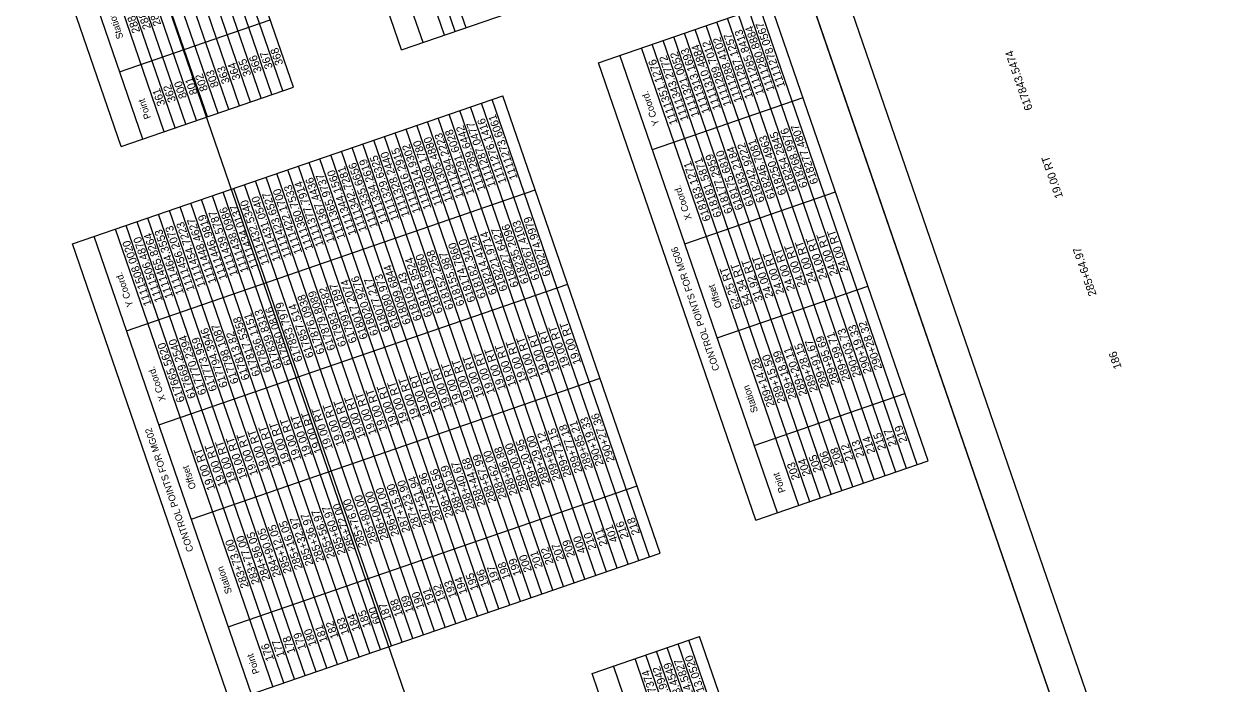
# Model space of a CAD drawing. Extents: x 1111039 to 1111836, y 617707 to 618808.
# Drawn here: x 1111305 to 1111836, y 618074 to 618364 of the extents above; entities that cross this region are included whole.
import ezdxf

# ---------------------------------------------------------------- set-up
doc = ezdxf.new("R2010")
doc.units = 0
for name, color, linetype in [('ANNOTATION', 7, 'Continuous'), ('BORDER', 7, 'Continuous'), ('CLIPS', 7, 'Continuous'), ('H_V CONTROLS', 7, 'Continuous'), ('PLOT BOUNDARY', 7, 'Continuous')]:
    doc.layers.add(name, color=color, linetype=linetype)

msp = doc.modelspace()

# ---------------------------------------------------------------- linework, layer by layer
at = {"layer": 'BORDER'}
msp.add_line((1111807.98, 617919.56), (1111547.52, 618675.97), dxfattribs=at)
at = {"layer": 'CLIPS'}
msp.add_lwpolyline([(1111807.98, 617919.56), (1111563.8, 618628.7), (1111310.4, 618541.44), (1111554.58, 617832.3)], close=True, dxfattribs=at)
at = {"layer": 'H_V CONTROLS'}
for p, q in [((1111494.82, 618360.94), (1111425.64, 618561.86)), ((1111499.55, 618362.57), (1111430.37, 618563.49)), ((1111480.64, 618356.06), (1111411.46, 618556.98)), ((1111490.09, 618359.31), (1111420.91, 618560.24)), ((1111471.18, 618352.8), (1111402, 618553.73)), ((1111418.96, 618334.82), (1111349.78, 618535.74)), ((1111423.69, 618336.45), (1111354.5, 618537.37)), ((1111423.69, 618336.45), (1111354.5, 618537.37)), ((1111404.78, 618329.94), (1111335.59, 618530.86)), ((1111409.51, 618331.56), (1111340.32, 618532.49)), ((1111414.23, 618333.19), (1111345.05, 618534.12)), ((1111390.59, 618325.05), (1111321.41, 618525.98)), ((1111395.32, 618326.68), (1111326.14, 618527.6)), ((1111400.05, 618328.31), (1111330.87, 618529.23)), ((1111371.68, 618318.54), (1111302.5, 618519.46)), ((1111376.41, 618320.17), (1111307.23, 618521.09)), ((1111381.14, 618321.8), (1111311.96, 618522.72)), ((1111385.87, 618323.43), (1111316.68, 618524.35)), ((1111357.5, 618313.66), (1111288.32, 618514.58)), ((1111366.96, 618316.91), (1111297.77, 618517.84)), ((1111348.05, 618310.4), (1111278.86, 618511.33)), ((1111471.18, 618352.8), (1111622.47, 618404.89)), ((1111557.73, 618347.19), (1111633.37, 618373.23)), ((1111697.82, 618170.68), (1111628.64, 618371.61)), ((1111702.55, 618172.31), (1111633.37, 618373.23)), ((1111702.55, 618172.31), (1111633.37, 618373.23)), ((1111347.33, 618343.21), (1111413.51, 618366)), ((1111683.64, 618165.8), (1111614.46, 618366.72)), ((1111688.37, 618167.43), (1111619.19, 618368.35)), ((1111693.1, 618169.06), (1111623.91, 618369.98)), ((1111669.46, 618160.92), (1111600.28, 618361.84)), ((1111674.19, 618162.54), (1111605, 618363.47)), ((1111678.91, 618164.17), (1111609.73, 618365.09)), ((1111650.55, 618154.4), (1111581.37, 618355.33)), ((1111655.28, 618156.03), (1111586.09, 618356.96)), ((1111660, 618157.66), (1111590.82, 618358.58)), ((1111664.73, 618159.29), (1111595.55, 618360.21)), ((1111636.37, 618149.52), (1111567.18, 618350.44)), ((1111645.82, 618152.78), (1111576.64, 618353.7)), ((1111626.91, 618146.27), (1111557.73, 618347.19)), ((1111348.05, 618310.4), (1111423.69, 618336.45)), ((1111326.61, 618267.61), (1111515.71, 618332.72)), ((1111575.44, 618128.54), (1111506.26, 618329.47)), ((1111580.17, 618130.17), (1111510.98, 618331.09)), ((1111584.9, 618131.8), (1111515.71, 618332.72)), ((1111584.9, 618131.8), (1111515.71, 618332.72)), ((1111581.43, 618309.08), (1111647.61, 618331.87)), ((1111561.26, 618123.66), (1111492.07, 618324.58)), ((1111565.98, 618125.29), (1111496.8, 618326.21)), ((1111570.71, 618126.91), (1111501.53, 618327.84)), ((1111542.35, 618117.15), (1111473.16, 618318.07)), ((1111547.07, 618118.78), (1111477.89, 618319.7)), ((1111551.8, 618120.4), (1111482.62, 618321.33)), ((1111556.53, 618122.03), (1111487.35, 618322.95)), ((1111528.16, 618112.26), (1111458.98, 618313.19)), ((1111532.89, 618113.89), (1111463.71, 618314.81)), ((1111537.62, 618115.52), (1111468.44, 618316.44)), ((1111513.98, 618107.38), (1111444.8, 618308.3)), ((1111518.71, 618109.01), (1111449.53, 618309.93)), ((1111523.44, 618110.64), (1111454.25, 618311.56)), ((1111499.8, 618102.5), (1111430.62, 618303.42)), ((1111504.53, 618104.12), (1111435.34, 618305.05)), ((1111509.25, 618105.75), (1111440.07, 618306.68)), ((1111480.89, 618095.99), (1111411.7, 618296.91)), ((1111485.62, 618097.61), (1111416.43, 618298.54)), ((1111490.34, 618099.24), (1111421.16, 618300.16)), ((1111495.07, 618100.87), (1111425.89, 618301.79)), ((1111350.31, 618229.5), (1111529.96, 618291.35)), ((1111466.71, 618091.1), (1111397.52, 618292.02)), ((1111471.43, 618092.73), (1111402.25, 618293.65)), ((1111476.16, 618094.36), (1111406.98, 618295.28)), ((1111452.52, 618086.22), (1111383.34, 618287.14)), ((1111457.25, 618087.85), (1111388.07, 618288.77)), ((1111461.98, 618089.47), (1111392.79, 618290.4)), ((1111595.67, 618267.71), (1111661.86, 618290.5)), ((1111438.34, 618081.34), (1111369.16, 618282.26)), ((1111443.07, 618082.96), (1111373.88, 618283.89)), ((1111447.79, 618084.59), (1111378.61, 618285.51)), ((1111419.43, 618074.82), (1111350.25, 618275.75)), ((1111424.16, 618076.45), (1111354.97, 618277.37)), ((1111428.88, 618078.08), (1111359.7, 618279)), ((1111433.61, 618079.71), (1111364.43, 618280.63)), ((1111405.25, 618069.94), (1111336.06, 618270.86)), ((1111414.7, 618073.2), (1111345.52, 618274.12)), ((1111395.79, 618066.68), (1111326.61, 618267.61)), ((1111364.55, 618188.13), (1111544.2, 618249.99)), ((1111609.91, 618226.34), (1111676.1, 618249.13)), ((1111378.79, 618146.76), (1111558.44, 618208.62)), ((1111626.19, 618179.07), (1111692.38, 618201.86)), ((1111626.91, 618146.27), (1111702.55, 618172.31)), ((1111395.07, 618099.49), (1111574.72, 618161.35)), ((1111395.79, 618066.68), (1111584.9, 618131.8)), ((1111554.89, 618079), (1111602.17, 618095.28)), ((1111671.35, 617894.36), (1111602.17, 618095.28)), ((1111671.35, 617894.36), (1111602.17, 618095.28)), ((1111657.17, 617889.47), (1111587.98, 618090.4)), ((1111661.89, 617891.1), (1111592.71, 618092.02)), ((1111666.62, 617892.73), (1111597.44, 618093.65)), ((1111642.98, 617884.59), (1111573.8, 618085.51)), ((1111647.71, 617886.22), (1111578.53, 618087.14)), ((1111652.44, 617887.85), (1111583.26, 618088.77)), ((1111633.53, 617881.33), (1111564.35, 618082.26)), ((1111624.07, 617878.08), (1111554.89, 618079))]:
    msp.add_line(p, q, dxfattribs=at)
at = {"layer": 'PLOT BOUNDARY'}
msp.add_lwpolyline([(1111835.61, 617886.27), (1111558.88, 618689.96), (1111038.85, 618510.9), (1111315.58, 617707.21)], close=True, dxfattribs=at)

# ---------------------------------------------------------------- texts
at = {"layer": 'ANNOTATION'}
for s, height, p in [('288+71.40', 3.516, (1111356.41, 618360.83)), ('288+79.37', 3.516, (1111361.15, 618362.47)), ('289+13.25', 3.45, (1111365.62, 618364)), ('1111285.8413', 3.5156, (1111630.49, 618333.68)), ('1111280.8884', 3.5156, (1111635.17, 618335.29)), ('1111278.0567', 3.5156, (1111639.81, 618336.89)), ('1111310.4884', 3.5156, (1111611.54, 618327.15)), ('1111289.7012', 3.5156, (1111616.26, 618328.78)), ('1111288.4102', 3.5156, (1111620.97, 618330.4)), ('1111287.1257', 3.5156, (1111625.73, 618332.04)), ('366', 3.516, (1111409.89, 618343.44)), ('367', 3.516, (1111414.72, 618345.11)), ('368', 3.516, (1111419.29, 618346.68)), ('1111343.2772', 3.5156, (1111597.38, 618322.28)), ('1111321.0052', 3.5156, (1111602.17, 618323.93)), ('1111313.1693', 3.5156, (1111606.82, 618325.53)), ('617843.5474', 3.5156, (1111748.59, 618326.93)), ('363', 3.516, (1111395.84, 618338.61)), ('364', 3.516, (1111400.53, 618340.22)), ('365', 3.516, (1111405.24, 618341.84)), ('1111351.1276', 3.5156, (1111592.58, 618320.63)), ('800', 3.516, (1111376.97, 618332.11)), ('801', 3.516, (1111381.74, 618333.75)), ('802', 3.516, (1111386.21, 618335.29)), ('803', 3.516, (1111390.98, 618336.93)), ('361', 3.516, (1111367.44, 618328.83)), ('362', 3.516, (1111372.17, 618330.46)), ('1111273.6061', 3.5156, (1111522.27, 618296.42)), ('1111291.6028', 3.5156, (1111503.24, 618289.86)), ('1111289.6442', 3.5156, (1111508.11, 618291.54)), ('1111287.0477', 3.5156, (1111512.68, 618293.11)), ('1111276.1416', 3.5156, (1111517.4, 618294.74)), ('618268.9976', 3.5156, (1111649.76, 618292.9)), ('618277.4807', 3.5156, (1111654.41, 618294.5)), ('1111308.1780', 3.5156, (1111489.16, 618285.02)), ('1111305.4880', 3.5156, (1111493.81, 618286.61)), ('1111294.2223', 3.5156, (1111498.6, 618288.27)), ('618246.7081', 3.5156, (1111635.57, 618288.01)), ('618250.4963', 3.5156, (1111640.33, 618289.65)), ('618254.2845', 3.5156, (1111645.08, 618291.29)), ('1111328.2440', 3.5156, (1111474.84, 618280.08)), ('1111316.2915', 3.5156, (1111479.64, 618281.74)), ('1111314.9302', 3.5156, (1111484.39, 618283.37)), ('618175.6810', 3.5156, (1111621.41, 618283.14)), ('618183.2184', 3.5156, (1111626.13, 618284.76)), ('618242.9222', 3.5156, (1111630.85, 618286.39)), ('1111335.6656', 3.5156, (1111460.8, 618275.25)), ('1111334.2619', 3.5156, (1111465.48, 618276.86)), ('1111329.6325', 3.5156, (1111470.19, 618278.48)), ('618183.1271', 3.5156, (1111607.18, 618278.24)), ('618181.5871', 3.5156, (1111611.97, 618279.89)), ('618177.2959', 3.5156, (1111616.77, 618281.54)), ('19.00 RT', 3.516, (1111761.9, 618288.3)), ('1111367.4436', 3.5156, (1111441.9, 618268.74)), ('1111365.9737', 3.5156, (1111446.51, 618270.33)), ('1111344.1560', 3.5156, (1111451.43, 618272.02)), ('1111342.7281', 3.5156, (1111456.02, 618273.6)), ('1111422.1700', 3.5156, (1111427.61, 618263.82)), ('1111380.7533', 3.5156, (1111432.43, 618265.48)), ('1111377.7914', 3.5156, (1111437.07, 618267.08)), ('1111432.5340', 3.5156, (1111413.23, 618258.87)), ('1111431.0540', 3.5156, (1111418.18, 618260.57)), ('1111423.6527', 3.5156, (1111422.93, 618262.21)), ('1111439.5787', 3.5156, (1111399.37, 618254.1)), ('1111438.0986', 3.5156, (1111404.06, 618255.71)), ('1111434.0137', 3.45, (1111408.56, 618257.24)), ('1111456.2073', 3.5156, (1111380.31, 618247.54)), ('1111454.7223', 3.5156, (1111385.14, 618249.2)), ('1111448.4627', 3.5156, (1111389.92, 618250.84)), ('1111446.9819', 3.5156, (1111394.66, 618252.47)), ('618235.2096', 3.5156, (1111527.28, 618250.73)), ('618267.4103', 3.5156, (1111532, 618252.35)), ('618274.9979', 3.5156, (1111536.87, 618254.03)), ('1111506.4870', 3.5156, (1111366.3, 618242.71)), ('1111465.8264', 3.5156, (1111370.91, 618244.3)), ('1111464.3553', 3.5156, (1111375.63, 618245.92)), ('618214.4124', 3.5156, (1111513.2, 618245.88)), ('618221.9714', 3.5156, (1111517.84, 618247.48)), ('618227.6427', 3.5156, (1111522.71, 618249.15)), ('24.00 RT', 3.516, (1111663.07, 618254.27)), ('24.00 RT', 3.516, (1111667.71, 618255.87)), ('1111508.0020', 3.5156, (1111361.46, 618241.05)), ('618152.2258', 3.5156, (1111494.23, 618239.35)), ('618174.7860', 3.5156, (1111503.76, 618242.63)), ('618182.3410', 3.5156, (1111508.4, 618244.23)), ('24.00 RT', 3.516, (1111644.15, 618247.76)), ('24.00 RT', 3.516, (1111648.87, 618249.38)), ('24.00 RT', 3.516, (1111653.63, 618251.02)), ('24.00 RT', 3.516, (1111658.38, 618252.66)), ('285+64.97', 3.516, (1111776.67, 618245.38)), ('618115.8524', 3.5156, (1111484.79, 618236.09)), ('618119.5960', 3.5156, (1111489.43, 618237.69)), ('618155.987', 3.516, (1111498.99, 618240.98)), ('31.92 RT', 3.516, (1111630.07, 618242.91)), ('24.00 RT', 3.516, (1111634.71, 618244.51)), ('24.00 RT', 3.516, (1111639.43, 618246.13)), ('618080.973', 3.516, (1111470.62, 618231.22)), ('618099.6844', 3.5156, (1111475.39, 618232.86)), ('618103.43', 3.516, (1111480.07, 618234.47)), ('62.25 RT', 3.516, (1111620.48, 618239.61)), ('54.34 RT', 3.516, (1111625.28, 618241.26)), ('617991.1897', 3.5156, (1111451.67, 618224.69)), ('618017.2074', 3.5156, (1111456.5, 618226.35)), ('618020.9276', 3.5156, (1111461.1, 618227.94)), ('618077.217', 3.516, (1111466.03, 618229.64)), ('617876.0938', 3.5156, (1111437.53, 618219.82)), ('617879.8089', 3.5156, (1111442.21, 618221.43)), ('617983.7582', 3.5156, (1111447.02, 618223.09)), ('617839.8313', 3.5156, (1111418.65, 618213.32)), ('617850.0816', 3.45, (1111423.15, 618214.87)), ('617853.7979', 3.5156, (1111427.83, 618216.48)), ('617857.514', 3.516, (1111432.77, 618218.18)), ('617817.5358', 3.5156, (1111409.25, 618210.09)), ('617836.1151', 3.5156, (1111413.97, 618211.71)), ('290+28.32', 3.516, (1111682.49, 618212.95)), ('617794.3946', 3.5156, (1111394.91, 618205.15)), ('617798.1087', 3.5156, (1111399.74, 618206.81)), ('617813.82', 3.516, (1111404.51, 618208.45)), ('19.00 RT', 3.516, (1111540.58, 618212.1)), ('19.00 RT', 3.516, (1111545.3, 618213.72)), ('19.00 RT', 3.516, (1111550.17, 618215.4)), ('289+99.71', 3.516, (1111668.41, 618208.1)), ('290+03.73', 3.516, (1111673.16, 618209.74)), ('290+19.33', 3.516, (1111677.84, 618211.35)), ('617665.5620', 3.5156, (1111376.06, 618198.66)), ('617669.2540', 3.5156, (1111380.9, 618200.32)), ('617770.2394', 3.5156, (1111385.51, 618201.91)), ('617773.959', 3.516, (1111390.23, 618203.53)), ('19.00 RT', 3.516, (1111521.7, 618205.6)), ('19.00 RT', 3.516, (1111526.5, 618207.25)), ('19.00 RT', 3.516, (1111531.14, 618208.85)), ('19.00 RT', 3.516, (1111536.01, 618210.52)), ('289+20.11', 3.516, (1111649.49, 618201.59)), ('289+28.15', 3.516, (1111654.21, 618203.22)), ('289+91.67', 3.516, (1111658.93, 618204.84)), ('289+95.69', 3.516, (1111663.65, 618206.47)), ('19.00 RT', 3.516, (1111507.53, 618200.72)), ('19.00 RT', 3.516, (1111512.29, 618202.35)), ('19.00 RT', 3.516, (1111517.06, 618204)), ('289+14.28', 3.516, (1111635.26, 618196.69)), ('289+15.50', 3.516, (1111640.05, 618198.34)), ('289+18.99', 3.516, (1111644.85, 618199.99)), ('186', 3.516, (1111787.7, 618213.37)), ('19.00 RT', 3.516, (1111493.38, 618195.84)), ('19.00 RT', 3.516, (1111498.09, 618197.46)), ('19.00 RT', 3.516, (1111502.73, 618199.06)), ('19.00 RT', 3.516, (1111479.33, 618191.01)), ('19.00 RT', 3.516, (1111483.92, 618192.59)), ('19.00 RT', 3.516, (1111488.69, 618194.23)), ('19.00 RT', 3.516, (1111460.32, 618184.46)), ('19.00 RT', 3.516, (1111464.97, 618186.06)), ('19.00 RT', 3.516, (1111469.8, 618187.72)), ('19.00 RT', 3.516, (1111474.41, 618189.31)), ('19.00 RT', 3.516, (1111446.07, 618179.55)), ('19.00 RT', 3.516, (1111450.83, 618181.19)), ('19.00 RT', 3.516, (1111455.51, 618182.8)), ('19.00 RT', 3.516, (1111431.95, 618174.69)), ('19.00 RT', 3.45, (1111436.45, 618176.24)), ('19.00 RT', 3.516, (1111441.13, 618177.85)), ('290+19.33', 3.516, (1111560.08, 618170.8)), ('290+27.36', 3.516, (1111564.94, 618172.48)), ('19.00 RT', 3.516, (1111413.04, 618168.18)), ('19.00 RT', 3.516, (1111417.81, 618169.82)), ('19.00 RT', 3.516, (1111422.55, 618171.46)), ('19.00 RT', 3.516, (1111427.27, 618173.08)), ('289+71.15', 3.516, (1111545.92, 618165.93)), ('289+77.18', 3.516, (1111550.79, 618167.6)), ('289+85.21', 3.516, (1111555.36, 618169.18)), ('217', 3.516, (1111688.87, 618179.34)), ('219', 3.516, (1111693.51, 618180.94)), ('19.00 RT', 3.516, (1111398.81, 618163.28)), ('19.00 RT', 3.516, (1111403.53, 618164.9)), ('19.00 RT', 3.516, (1111408.21, 618166.52)), ('289+00.90', 3.516, (1111527.07, 618159.44)), ('289+20.95', 3.516, (1111531.84, 618161.08)), ('289+29.00', 3.516, (1111536.48, 618162.68)), ('289+63.12', 3.516, (1111541.27, 618164.33)), ('212', 3.516, (1111669.95, 618172.83)), ('213', 3.516, (1111674.67, 618174.46)), ('214', 3.516, (1111679.43, 618176.09)), ('215', 3.516, (1111684.18, 618177.73)), ('19.00 RT', 3.516, (1111389.36, 618160.03)), ('19.00 RT', 3.516, (1111394.2, 618161.69)), ('288+57.99', 3.516, (1111512.87, 618154.55)), ('288+62.00', 3.516, (1111517.51, 618156.15)), ('288+96.88', 3.516, (1111522.31, 618157.8)), ('205', 3.516, (1111655.87, 618167.98)), ('206', 3.516, (1111660.51, 618169.58)), ('208', 3.516, (1111665.23, 618171.21)), ('288+20.59', 3.516, (1111498.7, 618149.67)), ('288+40.67', 3.516, (1111503.47, 618151.31)), ('288+44.68', 3.516, (1111508.15, 618152.92)), ('203', 3.516, (1111646.28, 618164.68)), ('204', 3.516, (1111651.08, 618166.33)), ('287+51.94', 3.516, (1111484.58, 618144.81)), ('287+55.96', 3.516, (1111489.18, 618146.39)), ('288+16.56', 3.516, (1111494.11, 618148.09)), ('286+00.00', 3.516, (1111465.61, 618138.27)), ('286+04.00', 3.516, (1111470.29, 618139.89)), ('287+15.90', 3.516, (1111475.1, 618141.54)), ('287+23.90', 3.516, (1111479.75, 618143.14)), ('285+72.00', 3.45, (1111451.23, 618133.32)), ('285+76.00', 3.516, (1111455.91, 618134.93)), ('285+80.00', 3.516, (1111460.85, 618136.64)), ('285+36.97', 3.516, (1111437.33, 618128.54)), ('285+56.97', 3.516, (1111442.05, 618130.16)), ('285+60.97', 3.516, (1111446.73, 618131.77)), ('285+12.05', 3.516, (1111422.99, 618123.6)), ('285+16.05', 3.516, (1111427.82, 618125.26)), ('285+32.97', 3.516, (1111432.59, 618126.91)), ('401', 3.516, (1111566.38, 618137.17)), ('216', 3.516, (1111571.1, 618138.79)), ('218', 3.516, (1111575.97, 618140.47)), ('283+73.00', 3.516, (1111404.14, 618117.11)), ('283+77.00', 3.516, (1111408.98, 618118.78)), ('284+86.05', 3.516, (1111413.59, 618120.36)), ('284+90.05', 3.516, (1111418.3, 618121.99)), ('209', 3.516, (1111547.5, 618130.67)), ('400', 3.516, (1111552.3, 618132.32)), ('210', 3.516, (1111556.94, 618133.92)), ('211', 3.516, (1111561.81, 618135.6)), ('201', 3.516, (1111533.33, 618125.79)), ('202', 3.516, (1111538.09, 618127.43)), ('207', 3.516, (1111542.86, 618129.07)), ('198', 3.516, (1111519.18, 618120.92)), ('199', 3.516, (1111523.89, 618122.54)), ('200', 3.516, (1111528.53, 618124.14)), ('195', 3.516, (1111505.13, 618116.08)), ('196', 3.516, (1111509.72, 618117.66)), ('197', 3.516, (1111514.49, 618119.3)), ('191', 3.516, (1111486.12, 618109.53)), ('192', 3.516, (1111490.77, 618111.13)), ('193', 3.516, (1111495.6, 618112.8)), ('194', 3.516, (1111500.21, 618114.38)), ('188', 3.516, (1111471.87, 618104.63)), ('189', 3.516, (1111476.63, 618106.27)), ('190', 3.516, (1111481.31, 618107.88)), ('185', 3.516, (1111457.75, 618099.77)), ('600', 3.45, (1111462.25, 618101.31)), ('187', 3.516, (1111466.93, 618102.93)), ('181', 3.516, (1111438.84, 618093.25)), ('182', 3.516, (1111443.61, 618094.9)), ('183', 3.516, (1111448.35, 618096.53)), ('184', 3.516, (1111453.07, 618098.15)), ('178', 3.516, (1111424.61, 618088.35)), ('179', 3.516, (1111429.33, 618089.98)), ('180', 3.516, (1111434.01, 618091.59)), ('176', 3.516, (1111415.16, 618085.1)), ('177', 3.516, (1111420, 618086.77)), ('1111513.0520', 3.5156, (1111608.64, 618058.94)), ('1111532.7374', 3.5156, (1111589.65, 618052.41)), ('1111524.9942', 3.5156, (1111594.44, 618054.06)), ('1111523.4549', 3.5156, (1111599.2, 618055.7)), ('1111514.5827', 3.5156, (1111603.9, 618057.31))]:
    msp.add_text(s, height=height, rotation=109, dxfattribs=at).set_placement(p)
at = {"layer": 'H_V CONTROLS'}
for s, p in [('Station', (1111349.03, 618358.22)), ('Y Coord.', (1111584.51, 618320.09)), ('Point', (1111361.15, 618323.04)), ('X Coord.', (1111598.75, 618278.73)), ('CONTROL POINTS FOR MG06', (1111610.99, 618212.47)), ('Y Coord.', (1111353.39, 618240.51)), ('Offset', (1111612.08, 618240.03)), ('X Coord.', (1111367.63, 618199.15)), ('Station', (1111627.9, 618194.08)), ('CONTROL POINTS FOR MG02', (1111379.84, 618132.96)), ('Offset', (1111380.96, 618160.45)), ('Point', (1111640.01, 618158.9)), ('Station', (1111396.78, 618114.5)), ('Point', (1111408.89, 618079.32))]:
    msp.add_text(s, height=3, rotation=109, dxfattribs=at).set_placement(p)

doc.saveas('drawing.dxf')
